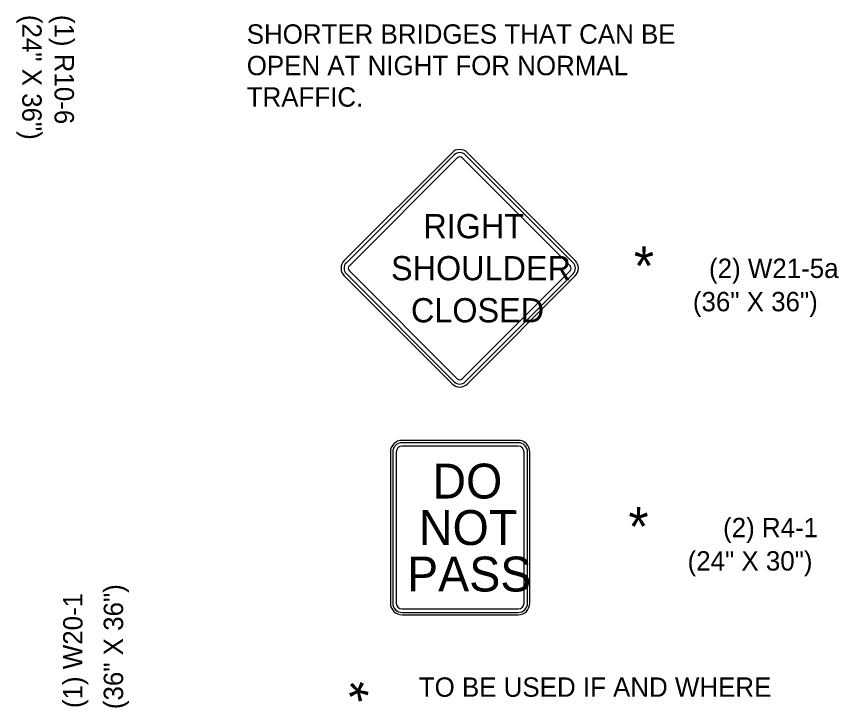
# Model space of a CAD drawing. Extents: x 1927831 to 1930787, y 596452 to 597699.
# Drawn here: x 1928599.1 to 1928853.8, y 597193.2 to 597407.3 of the extents above; entities that cross this region are included whole.
import ezdxf

# ---------------------------------------------------------------- set-up
doc = ezdxf.new("R2010")
doc.units = 0
for name, color, linetype in [('Default', 7, 'Continuous'), ('P_TC_Signs_Permanent', 7, 'Continuous'), ('P_TC_Signs_Temporary', 7, 'Continuous'), ('R_Border', 7, 'Continuous'), ('R_Border Prem', 7, 'Continuous')]:
    doc.layers.add(name, color=color, linetype=linetype)

msp = doc.modelspace()

# ---------------------------------------------------------------- linework, layer by layer
at = {"layer": 'P_TC_Signs_Permanent'}
for p, q in [((1928754.55, 597275.97), (1928718.55, 597275.97)), ((1928754.55, 597275.25), (1928718.55, 597275.25)), ((1928754.55, 597274.17), (1928718.55, 597274.17)), ((1928714.95, 597272.37), (1928714.95, 597225.57)), ((1928715.67, 597272.37), (1928715.67, 597225.57)), ((1928716.75, 597272.37), (1928716.75, 597225.57)), ((1928756.35, 597225.57), (1928756.35, 597272.37)), ((1928757.43, 597225.57), (1928757.43, 597272.37)), ((1928758.15, 597225.57), (1928758.15, 597272.37)), ((1928718.55, 597223.77), (1928754.55, 597223.77)), ((1928718.55, 597222.69), (1928754.55, 597222.69)), ((1928718.55, 597221.97), (1928754.55, 597221.97))]:
    msp.add_line(p, q, dxfattribs=at)
for centre, radius, start, end in [((1928718.55, 597272.37), 3.6, 90, 180), ((1928754.55, 597272.37), 3.6, 360, 90), ((1928718.55, 597272.37), 2.88, 90, 180), ((1928718.55, 597272.37), 1.8, 90, 180), ((1928754.55, 597272.37), 2.88, 360, 90), ((1928754.55, 597272.37), 1.8, 360, 90), ((1928718.55, 597225.57), 3.6, 180, 270), ((1928718.55, 597225.57), 2.88, 180, 270), ((1928718.55, 597225.57), 1.8, 180, 270), ((1928754.55, 597225.57), 3.6, 270, 360), ((1928754.55, 597225.57), 2.88, 270, 360), ((1928754.55, 597225.57), 1.8, 270, 360)]:
    msp.add_arc(centre, radius, start, end, dxfattribs=at)
at = {"layer": 'P_TC_Signs_Temporary'}
for p, q in [((1928700.64, 597331.67), (1928734.05, 597365.08)), ((1928738.82, 597365.08), (1928772.23, 597331.67)), ((1928701.3, 597331), (1928734.71, 597364.41)), ((1928702.23, 597330.07), (1928735.64, 597363.49)), ((1928737.23, 597363.49), (1928770.64, 597330.07)), ((1928738.16, 597364.41), (1928771.57, 597331)), ((1928734.05, 597293.48), (1928700.64, 597326.89)), ((1928734.71, 597294.14), (1928701.3, 597327.56)), ((1928735.64, 597295.07), (1928702.23, 597328.48)), ((1928770.64, 597328.48), (1928737.23, 597295.07)), ((1928771.57, 597327.56), (1928738.16, 597294.14)), ((1928772.23, 597326.89), (1928738.82, 597293.48))]:
    msp.add_line(p, q, dxfattribs=at)
for centre, radius, start, end in [((1928736.43, 597362.69), 3.38, 45, 135), ((1928736.43, 597362.69), 2.44, 45, 135), ((1928736.43, 597362.69), 1.13, 45, 135), ((1928703.02, 597329.28), 3.37, 135, 225), ((1928769.84, 597329.28), 3.37, 315, 45), ((1928703.02, 597329.28), 2.44, 135, 225), ((1928703.02, 597329.28), 1.12, 135, 225), ((1928769.84, 597329.28), 1.12, 315, 45), ((1928769.84, 597329.28), 2.44, 315, 45), ((1928736.43, 597295.87), 3.38, 225, 315), ((1928736.43, 597295.87), 2.44, 225, 315), ((1928736.43, 597295.87), 1.13, 225, 315)]:
    msp.add_arc(centre, radius, start, end, dxfattribs=at)

# ---------------------------------------------------------------- texts
at = {"layer": 'Default'}
for s, p in [('(36" X 36")', (1928632.12, 597192.73)), ('(1) W20-1', (1928619.55, 597193.06))]:
    msp.add_text(s, height=6, rotation=90, dxfattribs=at).set_placement(p)
at = {"layer": 'P_TC_Signs_Permanent'}
for s, rotation, p in [('DO', 360, (1928727.95, 597257.97)), ('NOT', 359.9596, (1928723.77, 597243.58)), ('PASS', 360, (1928720.1, 597229.17))]:
    msp.add_text(s, height=10.8, rotation=rotation, dxfattribs=at).set_placement(p)
at = {"layer": 'P_TC_Signs_Temporary'}
for s, p in [('RIGHT', (1928725.16, 597338.58)), ('SHOULDER', (1928715.14, 597325.56)), ('CLOSED', (1928721.32, 597312.53))]:
    msp.add_text(s, height=7.5, rotation=360, dxfattribs=at).set_placement(p)
at = {"layer": 'R_Border'}
for s, height, rotation, p in [('(24" X 36")', 5.9996, 270, (1928600.89, 597407.77)), ('(1) R10-6', 6, 270, (1928610.9, 597407.77)), ('SHORTER BRIDGES THAT CAN BE ', 6, 360, (1928670.44, 597398.83)), ('OPEN AT NIGHT FOR NORMAL ', 6, 360, (1928670.44, 597389.08)), ('TRAFFIC.', 6, 360, (1928670.44, 597379.33)), ('(2) W21-5a', 6, 360, (1928813.67, 597326.28)), ('(36" X 36")', 6, 360, (1928808.66, 597315.96)), ('(2) R4-1', 6, 360, (1928818.02, 597245.97)), ('(24" X 30")', 6, 360, (1928807.02, 597235.65)), ('TO BE USED IF AND WHERE', 6, 360, (1928723.75, 597196.56)), ('*', 12, 45, (1928709.04, 597189.82))]:
    msp.add_text(s, height=height, rotation=rotation, dxfattribs=at).set_placement(p)
at = {"layer": 'R_Border Prem'}
for p in [(1928790.38, 597324.03), (1928788.69, 597243.29)]:
    msp.add_text('*', height=12, rotation=360, dxfattribs=at).set_placement(p)

doc.saveas('drawing.dxf')
